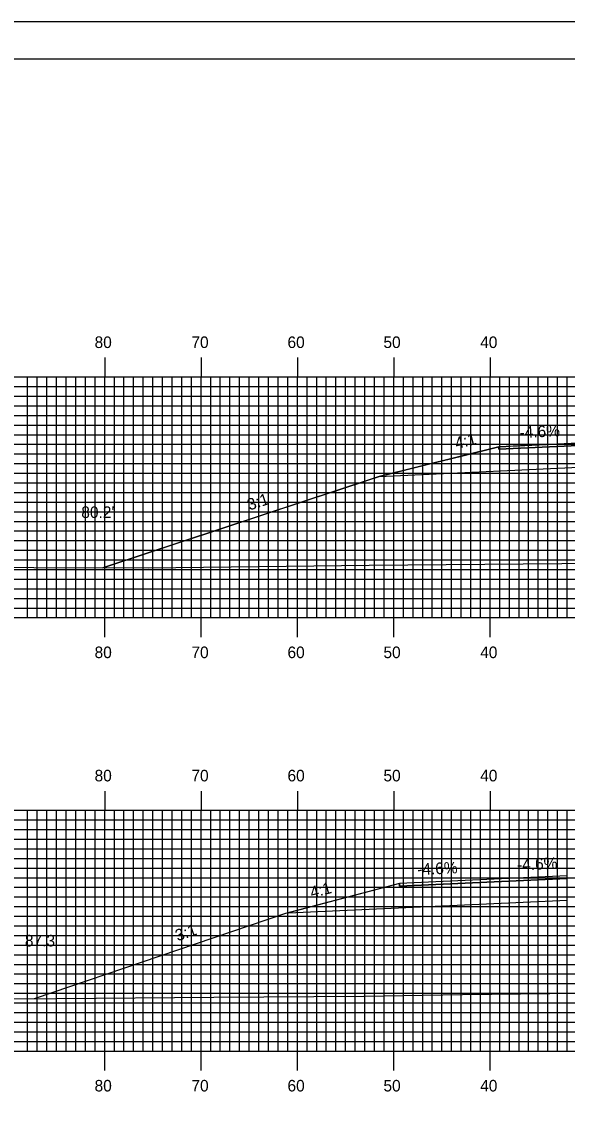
# Model space of a CAD drawing. Extents: x 1757069 to 1757412, y 442591 to 442811.
# Drawn here: x 1757146 to 1757202.6, y 442697.5 to 442810.5 of the extents above; entities that cross this region are included whole.
import ezdxf

# ---------------------------------------------------------------- set-up
doc = ezdxf.new("R2010")
doc.units = 0
for name, color, linetype in [('ANNOTATION', 7, 'Continuous'), ('BORDER', 7, 'Continuous'), ('D_Roadway_Centerline', 7, 'Continuous'), ('D_Roadway_Edge_Shoulder', 7, 'Continuous'), ('D_Roadway_SlopeLines', 7, 'Continuous'), ('D_Roadway_SubGrade', 7, 'Continuous'), ('D_Text_Standard', 7, 'Continuous'), ('H_V ANNOTATION', 7, 'Continuous'), ('MAJOR', 7, 'Continuous'), ('MINOR', 7, 'Continuous'), ('PLOT BOUNDARY', 7, 'Continuous'), ('S_Roadway_Centerline', 7, 'Continuous')]:
    doc.layers.add(name, color=color, linetype=linetype)

msp = doc.modelspace()

# ---------------------------------------------------------------- linework, layer by layer
at = {"layer": 'BORDER'}
msp.add_lwpolyline([(1757085, 442596.67), (1757405, 442596.67), (1757405, 442806.67), (1757085, 442806.67)], close=True, dxfattribs=at)
at = {"layer": 'D_Roadway_Centerline'}
msp.add_lwpolyline([(1757154.39, 442753.85), (1757160.46, 442755.86), (1757162.85, 442756.65), (1757165.1, 442757.39), (1757166.46, 442757.84), (1757170.6, 442759.21), (1757176.12, 442761.03), (1757177.19, 442761.38), (1757181.42, 442762.78), (1757181.79, 442762.9), (1757183.1, 442763.34), (1757183.3, 442763.39), (1757183.36, 442763.4), (1757187.09, 442764.32), (1757189.62, 442764.95), (1757191.78, 442765.48), (1757195.52, 442766.41), (1757196.24, 442766.44), (1757196.69, 442766.47), (1757200.46, 442766.64), (1757203.38, 442766.77)], dxfattribs=at)
at = {"layer": 'D_Roadway_Edge_Shoulder'}
for points in [[(1757206.79, 442766.93), (1757195.52, 442766.41), (1757195.52, 442766.16), (1757206.79, 442766.68)], [(1757202.61, 442721.85), (1757185.2, 442721.05), (1757185.2, 442720.8), (1757202.61, 442721.6)]]:
    msp.add_lwpolyline(points, close=True, dxfattribs=at)
at = {"layer": 'D_Roadway_SlopeLines'}
for points in [[(1757195.52, 442766.41), (1757183.1, 442763.34), (1757154.39, 442753.85)], [(1757185.2, 442721.05), (1757173.35, 442717.94), (1757147.27, 442709.1)]]:
    msp.add_lwpolyline(points, dxfattribs=at)
at = {"layer": 'D_Roadway_SubGrade'}
for points in [[(1757206.79, 442766.26), (1757206.79, 442766.68), (1757195.52, 442766.16), (1757195.52, 442766.41), (1757183.1, 442763.34), (1757206.79, 442764.43)], [(1757202.61, 442721.18), (1757202.61, 442721.6), (1757185.2, 442720.8), (1757185.2, 442721.05), (1757173.66, 442718.02), (1757202.61, 442719.35)]]:
    msp.add_lwpolyline(points, close=True, dxfattribs=at)
at = {"layer": 'MAJOR'}
for p, q in [((1757154.6, 442775.67), (1757154.6, 442773.67)), ((1757164.6, 442775.67), (1757164.6, 442773.67)), ((1757174.6, 442775.67), (1757174.6, 442773.67)), ((1757184.6, 442775.67), (1757184.6, 442773.67)), ((1757194.6, 442775.67), (1757194.6, 442773.67)), ((1757094.6, 442773.67), (1757374.6, 442773.67)), ((1757094.6, 442773.67), (1757374.6, 442773.67)), ((1757154.6, 442748.67), (1757154.6, 442773.67)), ((1757164.6, 442748.67), (1757164.6, 442773.67)), ((1757174.6, 442748.67), (1757174.6, 442773.67)), ((1757184.6, 442748.67), (1757184.6, 442773.67)), ((1757194.6, 442748.67), (1757194.6, 442773.67)), ((1757094.6, 442768.67), (1757374.6, 442768.67)), ((1757094.6, 442763.67), (1757374.6, 442763.67)), ((1757094.6, 442758.67), (1757374.6, 442758.67)), ((1757094.6, 442753.67), (1757374.6, 442753.67)), ((1757094.6, 442748.67), (1757374.6, 442748.67)), ((1757094.6, 442748.67), (1757374.6, 442748.67)), ((1757154.6, 442746.66), (1757154.6, 442748.67)), ((1757164.6, 442746.66), (1757164.6, 442748.67)), ((1757174.6, 442746.66), (1757174.6, 442748.67)), ((1757184.6, 442746.66), (1757184.6, 442748.67)), ((1757194.6, 442746.66), (1757194.6, 442748.67)), ((1757154.6, 442730.67), (1757154.6, 442728.67)), ((1757164.6, 442730.67), (1757164.6, 442728.67)), ((1757174.6, 442730.67), (1757174.6, 442728.67)), ((1757184.6, 442730.67), (1757184.6, 442728.67)), ((1757194.6, 442730.67), (1757194.6, 442728.67)), ((1757094.6, 442728.67), (1757374.6, 442728.67)), ((1757094.6, 442728.67), (1757374.6, 442728.67)), ((1757154.6, 442703.67), (1757154.6, 442728.67)), ((1757164.6, 442703.67), (1757164.6, 442728.67)), ((1757174.6, 442703.67), (1757174.6, 442728.67)), ((1757184.6, 442703.67), (1757184.6, 442728.67)), ((1757194.6, 442703.67), (1757194.6, 442728.67)), ((1757094.6, 442723.67), (1757374.6, 442723.67)), ((1757094.6, 442718.67), (1757374.6, 442718.67)), ((1757094.6, 442713.67), (1757374.6, 442713.67)), ((1757094.6, 442708.67), (1757374.6, 442708.67)), ((1757094.6, 442703.67), (1757374.6, 442703.67)), ((1757094.6, 442703.67), (1757374.6, 442703.67)), ((1757154.6, 442701.66), (1757154.6, 442703.67)), ((1757164.6, 442701.66), (1757164.6, 442703.67)), ((1757174.6, 442701.66), (1757174.6, 442703.67)), ((1757184.6, 442701.66), (1757184.6, 442703.67)), ((1757194.6, 442701.66), (1757194.6, 442703.67))]:
    msp.add_line(p, q, dxfattribs=at)
at = {"layer": 'MINOR'}
for p, q in [((1757146.6, 442748.67), (1757146.6, 442773.67)), ((1757147.6, 442748.67), (1757147.6, 442773.67)), ((1757148.6, 442748.67), (1757148.6, 442773.67)), ((1757149.6, 442748.67), (1757149.6, 442773.67)), ((1757150.6, 442748.67), (1757150.6, 442773.67)), ((1757151.6, 442748.67), (1757151.6, 442773.67)), ((1757152.6, 442748.67), (1757152.6, 442773.67)), ((1757153.6, 442748.67), (1757153.6, 442773.67)), ((1757155.6, 442748.67), (1757155.6, 442773.67)), ((1757156.6, 442748.67), (1757156.6, 442773.67)), ((1757157.6, 442748.67), (1757157.6, 442773.67)), ((1757158.6, 442748.67), (1757158.6, 442773.67)), ((1757159.6, 442748.67), (1757159.6, 442773.67)), ((1757160.6, 442748.67), (1757160.6, 442773.67)), ((1757161.6, 442748.67), (1757161.6, 442773.67)), ((1757162.6, 442748.67), (1757162.6, 442773.67)), ((1757163.6, 442748.67), (1757163.6, 442773.67)), ((1757165.6, 442748.67), (1757165.6, 442773.67)), ((1757166.6, 442748.67), (1757166.6, 442773.67)), ((1757167.6, 442748.67), (1757167.6, 442773.67)), ((1757168.6, 442748.67), (1757168.6, 442773.67)), ((1757169.6, 442748.67), (1757169.6, 442773.67)), ((1757170.6, 442748.67), (1757170.6, 442773.67)), ((1757171.6, 442748.67), (1757171.6, 442773.67)), ((1757172.6, 442748.67), (1757172.6, 442773.67)), ((1757173.6, 442748.67), (1757173.6, 442773.67)), ((1757175.6, 442748.67), (1757175.6, 442773.67)), ((1757176.6, 442748.67), (1757176.6, 442773.67)), ((1757177.6, 442748.67), (1757177.6, 442773.67)), ((1757178.6, 442748.67), (1757178.6, 442773.67)), ((1757179.6, 442748.67), (1757179.6, 442773.67)), ((1757180.6, 442748.67), (1757180.6, 442773.67)), ((1757181.6, 442748.67), (1757181.6, 442773.67)), ((1757182.6, 442748.67), (1757182.6, 442773.67)), ((1757183.6, 442748.67), (1757183.6, 442773.67)), ((1757185.6, 442748.67), (1757185.6, 442773.67)), ((1757186.6, 442748.67), (1757186.6, 442773.67)), ((1757187.6, 442748.67), (1757187.6, 442773.67)), ((1757188.6, 442748.67), (1757188.6, 442773.67)), ((1757189.6, 442748.67), (1757189.6, 442773.67)), ((1757190.6, 442748.67), (1757190.6, 442773.67)), ((1757191.6, 442748.67), (1757191.6, 442773.67)), ((1757192.6, 442748.67), (1757192.6, 442773.67)), ((1757193.6, 442748.67), (1757193.6, 442773.67)), ((1757195.6, 442748.67), (1757195.6, 442773.67)), ((1757196.6, 442748.67), (1757196.6, 442773.67)), ((1757197.6, 442748.67), (1757197.6, 442773.67)), ((1757198.6, 442748.67), (1757198.6, 442773.67)), ((1757199.6, 442748.67), (1757199.6, 442773.67)), ((1757200.6, 442748.67), (1757200.6, 442773.67)), ((1757201.6, 442748.67), (1757201.6, 442773.67)), ((1757202.6, 442748.67), (1757202.6, 442773.67)), ((1757094.6, 442772.67), (1757374.6, 442772.67)), ((1757094.6, 442771.67), (1757374.6, 442771.67)), ((1757094.6, 442770.67), (1757374.6, 442770.67)), ((1757094.6, 442769.67), (1757374.6, 442769.67)), ((1757094.6, 442767.67), (1757374.6, 442767.67)), ((1757094.6, 442766.67), (1757374.6, 442766.67)), ((1757094.6, 442765.67), (1757374.6, 442765.67)), ((1757094.6, 442764.67), (1757374.6, 442764.67)), ((1757094.6, 442762.67), (1757374.6, 442762.67)), ((1757094.6, 442761.67), (1757374.6, 442761.67)), ((1757094.6, 442760.67), (1757374.6, 442760.67)), ((1757094.6, 442759.67), (1757374.6, 442759.67)), ((1757094.6, 442757.67), (1757374.6, 442757.67)), ((1757094.6, 442756.67), (1757374.6, 442756.67)), ((1757094.6, 442755.67), (1757374.6, 442755.67)), ((1757094.6, 442754.67), (1757374.6, 442754.67)), ((1757094.6, 442752.67), (1757374.6, 442752.67)), ((1757094.6, 442751.67), (1757374.6, 442751.67)), ((1757094.6, 442750.67), (1757374.6, 442750.67)), ((1757094.6, 442749.67), (1757374.6, 442749.67)), ((1757146.6, 442703.67), (1757146.6, 442728.67)), ((1757147.6, 442703.67), (1757147.6, 442728.67)), ((1757148.6, 442703.67), (1757148.6, 442728.67)), ((1757149.6, 442703.67), (1757149.6, 442728.67)), ((1757150.6, 442703.67), (1757150.6, 442728.67)), ((1757151.6, 442703.67), (1757151.6, 442728.67)), ((1757152.6, 442703.67), (1757152.6, 442728.67)), ((1757153.6, 442703.67), (1757153.6, 442728.67)), ((1757155.6, 442703.67), (1757155.6, 442728.67)), ((1757156.6, 442703.67), (1757156.6, 442728.67)), ((1757157.6, 442703.67), (1757157.6, 442728.67)), ((1757158.6, 442703.67), (1757158.6, 442728.67)), ((1757159.6, 442703.67), (1757159.6, 442728.67)), ((1757160.6, 442703.67), (1757160.6, 442728.67)), ((1757161.6, 442703.67), (1757161.6, 442728.67)), ((1757162.6, 442703.67), (1757162.6, 442728.67)), ((1757163.6, 442703.67), (1757163.6, 442728.67)), ((1757165.6, 442703.67), (1757165.6, 442728.67)), ((1757166.6, 442703.67), (1757166.6, 442728.67)), ((1757167.6, 442703.67), (1757167.6, 442728.67)), ((1757168.6, 442703.67), (1757168.6, 442728.67)), ((1757169.6, 442703.67), (1757169.6, 442728.67)), ((1757170.6, 442703.67), (1757170.6, 442728.67)), ((1757171.6, 442703.67), (1757171.6, 442728.67)), ((1757172.6, 442703.67), (1757172.6, 442728.67)), ((1757173.6, 442703.67), (1757173.6, 442728.67)), ((1757175.6, 442703.67), (1757175.6, 442728.67)), ((1757176.6, 442703.67), (1757176.6, 442728.67)), ((1757177.6, 442703.67), (1757177.6, 442728.67)), ((1757178.6, 442703.67), (1757178.6, 442728.67)), ((1757179.6, 442703.67), (1757179.6, 442728.67)), ((1757180.6, 442703.67), (1757180.6, 442728.67)), ((1757181.6, 442703.67), (1757181.6, 442728.67)), ((1757182.6, 442703.67), (1757182.6, 442728.67)), ((1757183.6, 442703.67), (1757183.6, 442728.67)), ((1757185.6, 442703.67), (1757185.6, 442728.67)), ((1757186.6, 442703.67), (1757186.6, 442728.67)), ((1757187.6, 442703.67), (1757187.6, 442728.67)), ((1757188.6, 442703.67), (1757188.6, 442728.67)), ((1757189.6, 442703.67), (1757189.6, 442728.67)), ((1757190.6, 442703.67), (1757190.6, 442728.67)), ((1757191.6, 442703.67), (1757191.6, 442728.67)), ((1757192.6, 442703.67), (1757192.6, 442728.67)), ((1757193.6, 442703.67), (1757193.6, 442728.67)), ((1757195.6, 442703.67), (1757195.6, 442728.67)), ((1757196.6, 442703.67), (1757196.6, 442728.67)), ((1757197.6, 442703.67), (1757197.6, 442728.67)), ((1757198.6, 442703.67), (1757198.6, 442728.67)), ((1757199.6, 442703.67), (1757199.6, 442728.67)), ((1757200.6, 442703.67), (1757200.6, 442728.67)), ((1757201.6, 442703.67), (1757201.6, 442728.67)), ((1757202.6, 442703.67), (1757202.6, 442728.67)), ((1757094.6, 442727.67), (1757374.6, 442727.67)), ((1757094.6, 442726.67), (1757374.6, 442726.67)), ((1757094.6, 442725.67), (1757374.6, 442725.67)), ((1757094.6, 442724.67), (1757374.6, 442724.67)), ((1757094.6, 442722.67), (1757374.6, 442722.67)), ((1757094.6, 442721.67), (1757374.6, 442721.67)), ((1757094.6, 442720.67), (1757374.6, 442720.67)), ((1757094.6, 442719.67), (1757374.6, 442719.67)), ((1757094.6, 442717.67), (1757374.6, 442717.67)), ((1757094.6, 442716.67), (1757374.6, 442716.67)), ((1757094.6, 442715.67), (1757374.6, 442715.67)), ((1757094.6, 442714.67), (1757374.6, 442714.67)), ((1757094.6, 442712.67), (1757374.6, 442712.67)), ((1757094.6, 442711.67), (1757374.6, 442711.67)), ((1757094.6, 442710.67), (1757374.6, 442710.67)), ((1757094.6, 442709.67), (1757374.6, 442709.67)), ((1757094.6, 442707.67), (1757374.6, 442707.67)), ((1757094.6, 442706.67), (1757374.6, 442706.67)), ((1757094.6, 442705.67), (1757374.6, 442705.67)), ((1757094.6, 442704.67), (1757374.6, 442704.67))]:
    msp.add_line(p, q, dxfattribs=at)
at = {"layer": 'PLOT BOUNDARY'}
msp.add_lwpolyline([(1757068.81, 442590.55), (1757408.81, 442590.55), (1757408.81, 442810.55), (1757068.81, 442810.55)], close=True, dxfattribs=at)
at = {"layer": 'S_Roadway_Centerline'}
for points in [[(1757094.6, 442753.7), (1757106.02, 442753.69), (1757125.8, 442753.96), (1757135.34, 442753.91), (1757159.12, 442753.84), (1757182.03, 442754.12), (1757202.03, 442754.31), (1757204.09, 442754.32), (1757230.57, 442754.75), (1757249.03, 442754.84), (1757258.63, 442754.86), (1757284.4, 442755.15), (1757295.54, 442755.17), (1757319.95, 442754.95), (1757333.06, 442754.89), (1757374.6, 442754.64)], [(1757094.6, 442709.18), (1757117.33, 442709.26), (1757140.81, 442709.08), (1757149.64, 442709.11), (1757165.92, 442709.27), (1757181.5, 442709.37), (1757191.75, 442709.55), (1757206.83, 442709.71), (1757242.69, 442709.94), (1757244.49, 442709.95), (1757245.67, 442709.95), (1757285.02, 442710.21), (1757285.15, 442710.21), (1757316.08, 442710.1), (1757319.99, 442710.08), (1757358.79, 442710.05), (1757374.6, 442710.01)]]:
    msp.add_lwpolyline(points, dxfattribs=at)

# ---------------------------------------------------------------- texts
at = {"layer": 'ANNOTATION'}
for s, rotation, p in [('4:1', 13.9011, (1757191.11, 442766.18)), ('-4.6%', 2.6415, (1757197.68, 442767.31)), ('3:1', 18.2821, (1757169.63, 442759.79)), ('-4.6%', 2.6208, (1757197.42, 442722.41)), ('-4.6%', 2.6204, (1757187.06, 442721.94)), ('4:1', 14.7463, (1757176.09, 442719.53)), ('3:1', 18.7281, (1757162.16, 442715.06))]:
    msp.add_text(s, height=1.2, rotation=rotation, dxfattribs=at).set_placement(p)
at = {"layer": 'D_Text_Standard'}
for s, p in [("80.2'", (1757152.17, 442759.02)), ("87.3'", (1757146.32, 442714.53))]:
    msp.add_text(s, height=1.2, dxfattribs=at).set_placement(p)
at = {"layer": 'H_V ANNOTATION'}
for s, p in [('80', (1757153.55, 442776.67)), ('70', (1757163.6, 442776.67)), ('60', (1757173.57, 442776.67)), ('50', (1757183.53, 442776.67)), ('40', (1757193.57, 442776.67)), ('80', (1757153.55, 442744.47)), ('70', (1757163.6, 442744.47)), ('60', (1757173.57, 442744.47)), ('50', (1757183.53, 442744.47)), ('40', (1757193.57, 442744.47)), ('80', (1757153.55, 442731.67)), ('70', (1757163.6, 442731.67)), ('60', (1757173.57, 442731.67)), ('50', (1757183.53, 442731.67)), ('40', (1757193.57, 442731.67)), ('80', (1757153.55, 442699.47)), ('70', (1757163.6, 442699.47)), ('60', (1757173.57, 442699.47)), ('50', (1757183.53, 442699.47)), ('40', (1757193.57, 442699.47))]:
    msp.add_text(s, height=1.2, dxfattribs=at).set_placement(p)

doc.saveas('drawing.dxf')
